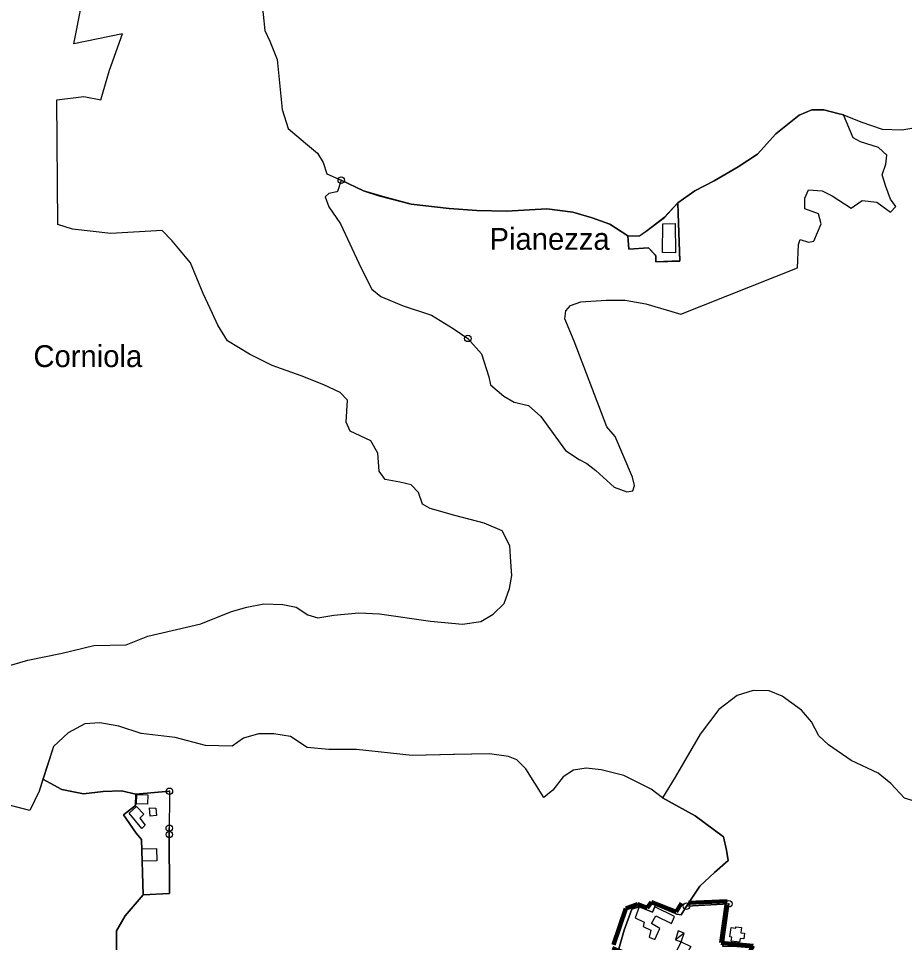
# Model space of a CAD drawing. Extents: x 645880 to 658994, y 884400 to 894744.
# Drawn here: x 655833 to 656523, y 890454 to 891174 of the extents above; entities that cross this region are included whole.
import ezdxf
from ezdxf.enums import TextEntityAlignment as Align

# ---------------------------------------------------------------- set-up
doc = ezdxf.new("R2010")
doc.units = 0
doc.header["$LTSCALE"] = 10
doc.header["$PDMODE"] = 32
doc.header["$PDSIZE"] = 5
doc.linetypes.add('MEDIUM_DASHED', pattern=[4.5, 3, -1.5])
for name, color, linetype, lineweight in [('1', 7, 'Continuous', 25), ('15', 7, 'MEDIUM_DASHED', 100), ('16', 7, 'Continuous', 25), ('18', 7, 'Continuous', 25), ('4', 7, 'Continuous', 25), ('6', 7, 'Continuous', 25)]:
    doc.layers.add(name, color=color, linetype=linetype, lineweight=lineweight)
doc.layers.add('60', color=7, linetype='Continuous')

msp = doc.modelspace()

# ---------------------------------------------------------------- linework, layer by layer
at = {"layer": '1'}
msp.add_line((656351.51, 890461.61), (656344.76, 890456.42), dxfattribs=at)
for points in [[(656316.6, 890482.09), (656310.86, 890480.17), (656304.84, 890463.75), (656300.81, 890449.21), (656323.09, 890440.57), (656323.73, 890436.19), (656329.95, 890433.47)], [(656405.68, 890449.96), (656389.24, 890451.06), (656381.68, 890451.17), (656386.34, 890484.41), (656353.4, 890482.51), (656349.21, 890475.84), (656345.83, 890476.36), (656329.38, 890483.21), (656326.8, 890477.93), (656316.6, 890482.09)]]:
    msp.add_lwpolyline(points, dxfattribs=at)
for points in [[(656316.6, 890482.09), (656313.35, 890473.44), (656320.38, 890469.97), (656319.66, 890466.8), (656325.73, 890463.8), (656324.31, 890458.49), (656328.63, 890456.66), (656332.61, 890465.13), (656326.16, 890469.05), (656329.4, 890475.07), (656341.7, 890469.11), (656344.17, 890474.39), (656328.63, 890481.92), (656326.8, 890477.93)], [(656344.76, 890456.42), (656349.18, 890454.85), (656351.51, 890461.61), (656346.96, 890463.4)], [(656350.13, 890439.21), (656343.19, 890442.63), (656349.15, 890454.85), (656356.76, 890451.16)]]:
    msp.add_lwpolyline(points, close=True, dxfattribs=at)
at = {"layer": '15'}
msp.add_lwpolyline([(656326.91, 890431.81), (656332.62, 890438.94), (656354.72, 890428.62), (656352.4, 890422.3), (656367.55, 890416.83), (656382.07, 890417.25), (656391.12, 890427.78), (656405.22, 890451.78), (656380.39, 890453.89), (656385.02, 890486.31), (656349.54, 890484.92), (656345.25, 890478.1), (656326.1, 890485.68), (656322.73, 890481.26), (656315.36, 890484.21), (656306.1, 890480.84), (656295.79, 890450.1), (656318.73, 890439.78), (656320.46, 890435.07)], close=True, dxfattribs=at)
at = {"layer": '16'}
msp.add_line((656386.34, 890484.41), (656381.68, 890451.17), dxfattribs=at)
for points in [[(656107.51, 890844.89), (656091.53, 890852.4), (656088.44, 890859.4), (656089.47, 890876.4), (656083.8, 890882.4), (656070.91, 890888.4), (656053.38, 890895.4), (656030.7, 890903.41), (656013.18, 890912.12), (655996, 890922.49), (655988.42, 890934.91), (655984.3, 890943.92), (655977.08, 890959.42), (655967.29, 890983.42), (655952.85, 891000.43), (655945.15, 891008.51), (655905.11, 891006.15), (655875.32, 891009.61), (655863.98, 891013.11), (655863.11, 891110.32), (655884.21, 891112.73), (655897.47, 891110.32), (655904.1, 891133.25), (655914.35, 891161.62), (655876.33, 891153.86), (655882.51, 891185.32)], [(656022.57, 891189.45), (656025.05, 891164.29), (656028.95, 891155.9), (656034.63, 891141.71), (656038.53, 891102.67), (656043.15, 891087.83), (656056.63, 891076.54), (656066.21, 891068.79)], [(656346.76, 891030.15), (656359.82, 891039.27), (656374.91, 891047.18), (656393.59, 891057.96), (656408.69, 891068.03), (656423.06, 891083.85), (656441.02, 891098.23), (656451.08, 891102.54), (656460.42, 891102.54), (656471.2, 891099.67), (656475.55, 891098.58), (656489.19, 891092.99), (656505.69, 891087.49), (656521.15, 891086.99), (656530.43, 891088.49), (656539.2, 891093.99), (656550.54, 891114), (656575.8, 891148.01)], [(656471.2, 891099.67), (656460.42, 891102.54), (656451.08, 891102.54), (656441.02, 891098.23), (656423.06, 891083.85), (656408.69, 891068.03), (656393.59, 891057.96), (656374.91, 891047.18), (656359.82, 891039.27), (656346.76, 891030.15), (656346.97, 891021.75), (656347.02, 891021.8), (656348.15, 890984.82), (656329.53, 890984.13), (656329.53, 890988.93), (656323.82, 890995.11), (656308.49, 890993.97), (656307.81, 891004.27)], [(656466.77, 891035.6), (656481.67, 891025.92), (656490.18, 891031.73), (656501.54, 891030.43), (656512.18, 891022.69), (656516.44, 891027.21), (656512.18, 891033.02), (656508.63, 891042.69), (656505.79, 891051.73), (656508.63, 891060.12), (656509.34, 891067.21), (656502.95, 891073.02), (656488.76, 891077.54), (656483.09, 891080.76), (656475.55, 891098.58), (656471.2, 891099.67)], [(656066.21, 891068.79), (656070.39, 891061.56), (656073.22, 891052.53), (656084.58, 891047.69)], [(656116.93, 891034.95), (656101.84, 891039.27), (656084.58, 891047.69), (656081.74, 891038.98), (656081.03, 891038.65), (656075, 891037.36), (656072.16, 891034.78), (656075, 891027.04), (656083.87, 891013.81), (656100.19, 890979.29), (656108.35, 890962.84), (656115.44, 890957.03), (656132.76, 890949.96), (656154.75, 890942.54), (656171.78, 890932.22), (656183.14, 890924.48)], [(656084.58, 891047.69), (656101.84, 891039.27), (656113.9, 891035.54), (656139.05, 891029.07)], [(656183.14, 890924.48), (656193.78, 890912.54), (656199.46, 890894.48), (656200.88, 890888.35), (656211.17, 890879.63), (656219.33, 890874.8), (656230.32, 890872.21), (656239.9, 890863.83), (656259.06, 890837.37), (656269.71, 890830.27), (656275.74, 890827.05), (656282.83, 890821.56), (656297.03, 890808.66), (656306.96, 890805.11), (656311.57, 890805.76), (656312.99, 890809.95), (656311.22, 890816.4), (656297.73, 890848.02), (656291.35, 890855.76), (656265.83, 890922.44), (656258.73, 890939.86), (656259.44, 890945.99), (656262.99, 890950.18), (656271.15, 890953.09), (656290.75, 890954.4), (656305.7, 890954.4), (656321.68, 890951.4), (656348.97, 890943.33), (656439.8, 890979.46), (656440.51, 890997.53), (656441.93, 891001.4), (656448.32, 890999.46), (656452.57, 891000.11), (656458.25, 891013.66), (656456.12, 891021.4), (656445.48, 891025.27), (656445.48, 891033.66), (656448.32, 891040.11), (656458.96, 891039.47), (656466.77, 891035.6)], [(656190.08, 891024.04), (656168.67, 891025.61), (656139.05, 891029.07), (656116.93, 891034.95)], [(656139.05, 891029.07), (656168.67, 891025.61), (656190.08, 891024.04), (656213.23, 891023.45), (656244.69, 891025.48), (656264.97, 891022.73), (656280.06, 891018.42), (656293.71, 891013.38), (656307.81, 891004.27), (656316.73, 891004.27), (656322.67, 891008.39), (656336.16, 891018.69), (656346.76, 891030.15)], [(656307.81, 891004.27), (656293.71, 891013.38), (656280.06, 891018.42), (656264.97, 891022.73), (656244.69, 891025.48), (656213.23, 891023.45), (656190.08, 891024.04)], [(655792.34, 890660.05), (655840.64, 890674.02), (655867.17, 890679.45), (655892.03, 890685.35), (655917.21, 890686.09), (655934.03, 890692.7), (655975.29, 890702.29), (655999.14, 890712.01), (656010.98, 890715.31), (656024.41, 890717.97), (656038.96, 890717.41), (656049.45, 890715.17), (656058.55, 890709.29), (656066.25, 890707.05), (656078.7, 890709.01), (656098.15, 890710.97), (656114.24, 890710.13), (656154.01, 890704.34), (656178.9, 890702.01), (656193.15, 890704.08), (656202.75, 890709.79), (656211.3, 890718.09), (656215.45, 890729.77), (656217.27, 890739.88), (656216.49, 890750.52), (656215.76, 890763.07), (656209.75, 890774.65), (656195.75, 890780.62), (656172.97, 890786.57), (656153.9, 890792.07), (656147.71, 890795.57), (656144.62, 890804.57), (656138.95, 890810.58), (656130.18, 890812.58), (656118.84, 890814.58), (656114.2, 890821.08), (656113.17, 890835.08), (656107.51, 890844.89)], [(656535.88, 890562.67), (656523.1, 890566.68), (656512.58, 890577.96), (656502.75, 890586.03), (656481.61, 890596.03), (656464.08, 890608.04), (656456.35, 890615.04), (656450.68, 890626.04), (656442.94, 890635.04), (656427.99, 890646.04), (656417.68, 890650.04), (656405.31, 890650.54), (656392.94, 890646.54), (656378.5, 890635.54), (656364.13, 890616.47), (656344.54, 890582.96), (656334.72, 890566.93)], [(656228.32, 890589.55), (656221.24, 890596.51), (656214.92, 890599.06), (656200.11, 890601.09), (656171.99, 890600.59), (656139.82, 890599.76), (656096.48, 890604.59), (656074.95, 890604.53), (656058.16, 890606.03), (656044.93, 890614.6), (656032.04, 890616.6), (656020.18, 890616.6), (656008.57, 890613.31), (655999.55, 890607.04), (655978.76, 890607.54), (655955.21, 890613.81), (655928.66, 890616.82), (655911.37, 890622.58), (655896.59, 890625.34), (655884.87, 890624.5), (655871.98, 890617.5), (655860.52, 890606.79), (655852.28, 890581.39)], [(656353.4, 890482.51), (656363.66, 890498.23), (656375.28, 890508.69), (656385.73, 890517.99), (656384.57, 890526.12), (656382.25, 890536.58), (656360.18, 890552.86), (656334.72, 890566.93), (656325.76, 890573.55), (656304.66, 890584.23), (656286.87, 890588.74), (656275.35, 890589.99), (656265.33, 890588.49), (656257.31, 890583.22), (656249.3, 890572.95), (656242.24, 890567.05), (656228.32, 890589.55)], [(655899.22, 890571.74), (655883.91, 890570.04), (655866.9, 890573.44), (655852.28, 890581.39), (655849.3, 890571.99), (655842.21, 890557.03), (655811.7, 890564.82)], [(655852.28, 890581.39), (655866.9, 890573.44), (655883.91, 890570.04), (655899.22, 890571.74), (655913.39, 890572.31), (655924.68, 890569.8), (655950.79, 890571.98), (655950.69, 890538.37)], [(655915.26, 890336.66), (655917.59, 890354.1), (655917.59, 890383.15), (655921.07, 890399.43), (655915.26, 890415.7), (655909.46, 890436.62), (655909.46, 890463.36), (655916.43, 890474.98), (655930.3, 890491.47), (655928.97, 890534.53), (655925.01, 890539.27), (655915.12, 890553.65), (655924.48, 890560.83), (655924.68, 890569.8), (655913.39, 890572.31), (655899.22, 890571.74)], [(656334.72, 890566.93), (656360.18, 890552.86), (656382.25, 890536.58), (656384.57, 890526.12), (656385.73, 890517.99), (656375.28, 890508.69), (656363.66, 890498.23), (656353.4, 890482.51), (656386.34, 890484.41)], [(655950.69, 890538.37), (655950.79, 890492.47), (655930.3, 890491.47)], [(655930.3, 890491.47), (655916.43, 890474.98), (655909.46, 890463.36), (655909.46, 890436.62), (655915.26, 890415.7), (655921.07, 890399.43), (655917.59, 890383.15), (655917.59, 890354.1), (655915.26, 890336.66), (655908.48, 890319.27)], [(656300.81, 890449.21), (656304.84, 890463.75), (656310.86, 890480.17), (656315.7, 890481.79)], [(656315.7, 890481.79), (656315.81, 890482.09), (656316.17, 890481.94)], [(656316.17, 890481.94), (656316.6, 890482.09), (656326.8, 890477.93), (656329.38, 890483.21)], [(656329.38, 890483.21), (656345.83, 890476.36), (656349.21, 890475.84), (656353.4, 890482.51)]]:
    msp.add_lwpolyline(points, dxfattribs=at)
for p in [(656084.58, 891047.69), (656183.14, 890924.48), (655950.69, 890538.37), (656386.34, 890484.41), (656353.4, 890482.51)]:
    msp.add_point(p, dxfattribs=at)
at = {"layer": '18'}
for points in [[(655863.98, 891013.11), (655863.11, 891110.32), (655884.21, 891112.73), (655897.47, 891110.32), (655904.1, 891133.25), (655914.35, 891161.62), (655876.33, 891153.86), (655882.51, 891185.32)], [(656022.57, 891189.45), (656025.05, 891164.29), (656028.95, 891155.9), (656034.63, 891141.71), (656038.53, 891102.67), (656043.15, 891087.83), (656056.63, 891076.54), (656066.21, 891068.79), (656070.39, 891061.56), (656073.22, 891052.53), (656084.58, 891047.69), (656081.74, 891038.98), (656081.03, 891038.65), (656075, 891037.36), (656072.16, 891034.78), (656075, 891027.04), (656083.87, 891013.81), (656100.19, 890979.29), (656108.35, 890962.84), (656115.44, 890957.03), (656132.76, 890949.96), (656154.75, 890942.54), (656171.78, 890932.22), (656183.14, 890924.48), (656193.78, 890912.54), (656199.46, 890894.48)], [(656490.18, 891031.73), (656501.54, 891030.43), (656512.18, 891022.69), (656516.44, 891027.21), (656512.18, 891033.02), (656508.63, 891042.69), (656505.79, 891051.73), (656508.63, 891060.12), (656509.34, 891067.21), (656502.95, 891073.02), (656488.76, 891077.54), (656483.09, 891080.76), (656475.55, 891098.58), (656489.19, 891092.99), (656505.69, 891087.49), (656521.15, 891086.99), (656530.43, 891088.49)], [(656199.46, 890894.48), (656200.88, 890888.35), (656211.17, 890879.63), (656219.33, 890874.8), (656230.32, 890872.21), (656239.9, 890863.83), (656259.06, 890837.37), (656269.71, 890830.27), (656275.74, 890827.05), (656282.83, 890821.56), (656297.03, 890808.66), (656306.96, 890805.11), (656311.57, 890805.76), (656312.99, 890809.95), (656311.22, 890816.4), (656297.73, 890848.02), (656291.35, 890855.76), (656265.83, 890922.44), (656258.73, 890939.86), (656259.44, 890945.99), (656262.99, 890950.18), (656271.15, 890953.09), (656290.75, 890954.4), (656305.7, 890954.4), (656321.68, 890951.4), (656348.97, 890943.33), (656439.8, 890979.46), (656440.51, 890997.53), (656441.93, 891001.4), (656448.32, 890999.46), (656452.57, 891000.11), (656458.25, 891013.66), (656456.12, 891021.4), (656445.48, 891025.27), (656445.48, 891033.66), (656448.32, 891040.11), (656458.96, 891039.47), (656466.77, 891035.6), (656481.67, 891025.92), (656490.18, 891031.73)], [(656107.51, 890844.89), (656091.53, 890852.4), (656088.44, 890859.4), (656089.47, 890876.4), (656083.8, 890882.4), (656070.91, 890888.4), (656053.38, 890895.4), (656030.7, 890903.41), (656013.18, 890912.12), (655996, 890922.49), (655988.42, 890934.91), (655984.3, 890943.92), (655977.08, 890959.42), (655967.29, 890983.42), (655952.85, 891000.43), (655945.15, 891008.51), (655905.11, 891006.15), (655875.32, 891009.61), (655863.98, 891013.11)], [(655792.34, 890660.05), (655840.64, 890674.02), (655867.17, 890679.45), (655892.03, 890685.35), (655917.21, 890686.09), (655934.03, 890692.7), (655975.29, 890702.29), (655999.14, 890712.01), (656010.98, 890715.31), (656024.41, 890717.97), (656038.96, 890717.41), (656049.45, 890715.17), (656058.55, 890709.29), (656066.25, 890707.05), (656078.7, 890709.01), (656098.15, 890710.97), (656114.24, 890710.13), (656154.01, 890704.34), (656178.9, 890702.01), (656193.15, 890704.08), (656202.75, 890709.79), (656211.3, 890718.09), (656215.45, 890729.77), (656217.27, 890739.88), (656216.49, 890750.52), (656215.76, 890763.07), (656209.75, 890774.65), (656195.75, 890780.62), (656172.97, 890786.57), (656153.9, 890792.07), (656147.71, 890795.57), (656144.62, 890804.57), (656138.95, 890810.58), (656130.18, 890812.58), (656118.84, 890814.58), (656114.2, 890821.08), (656113.17, 890835.08), (656107.51, 890844.89)], [(656535.88, 890562.67), (656523.1, 890566.68), (656512.58, 890577.96), (656502.75, 890586.03), (656481.61, 890596.03), (656464.08, 890608.04), (656456.35, 890615.04), (656450.68, 890626.04), (656442.94, 890635.04), (656427.99, 890646.04), (656417.68, 890650.04), (656405.31, 890650.54), (656392.94, 890646.54), (656378.5, 890635.54), (656364.13, 890616.47), (656344.54, 890582.96), (656334.72, 890566.93), (656325.76, 890573.55), (656304.66, 890584.23), (656286.87, 890588.74), (656275.35, 890589.99), (656265.33, 890588.49), (656257.31, 890583.22), (656249.3, 890572.95), (656242.24, 890567.05), (656228.32, 890589.55)], [(656228.32, 890589.55), (656221.24, 890596.51), (656214.92, 890599.06), (656200.11, 890601.09), (656172.78, 890600.59), (656139.82, 890599.76), (656096.48, 890604.59), (656074.95, 890604.53), (656058.16, 890606.03), (656044.93, 890614.6), (656032.04, 890616.6), (656020.18, 890616.6), (656008.57, 890613.31), (655999.55, 890607.04), (655978.76, 890607.54), (655955.21, 890613.81), (655928.66, 890616.82), (655911.37, 890622.58), (655896.59, 890625.34), (655884.87, 890624.5), (655871.98, 890617.5), (655860.52, 890606.79), (655855.51, 890591.25), (655849.3, 890571.99), (655842.21, 890557.03), (655811.7, 890564.82)]]:
    msp.add_lwpolyline(points, dxfattribs=at)
at = {"layer": '4'}
for points in [[(656346.91, 891021.65), (656346.7, 891030.05), (656336.1, 891018.59), (656322.61, 891008.29), (656316.67, 891004.17), (656307.75, 891004.17), (656308.43, 890993.87), (656323.76, 890995.01), (656329.47, 890988.83), (656329.47, 890984.03)], [(656329.47, 890984.03), (656348.09, 890984.72), (656346.96, 891021.7)], [(655950.79, 890571.98), (655924.68, 890569.8), (655924.48, 890560.83), (655915.12, 890553.65), (655925.01, 890539.27), (655928.97, 890534.53)], [(655928.97, 890534.53), (655930.3, 890491.47), (655950.79, 890492.47), (655950.69, 890538.37), (655950.68, 890543.22)]]:
    msp.add_lwpolyline(points, dxfattribs=at)
for points in [[(656335.02, 891013.64), (656344.44, 891013.88), (656344.92, 890991.18), (656334.78, 890991.42)], [(655925.36, 890569.4), (655933.85, 890569.2), (655933.65, 890562.03), (655925.28, 890562.23)], [(655925.28, 890560.03), (655930.86, 890554.25), (655927.67, 890551.06), (655931.8, 890545.64), (655929.2, 890543.03), (655919.5, 890555.05)], [(655935.32, 890558.97), (655940.23, 890558.84), (655940.69, 890553), (655935.78, 890552.69)], [(655929.47, 890527.13), (655940.82, 890527.33), (655941.02, 890517.76), (655929.67, 890517.56)]]:
    msp.add_lwpolyline(points, close=True, dxfattribs=at)
for p in [(655950.79, 890571.98), (655950.68, 890543.22)]:
    msp.add_point(p, dxfattribs=at)
at = {"layer": '6'}
msp.add_lwpolyline([(656387.15, 890458.59), (656388.22, 890466.01), (656391.68, 890465.51), (656391.83, 890466.5), (656396.28, 890465.86), (656395.71, 890461.9), (656398.68, 890461.48), (656398.04, 890457.02), (656395.07, 890457.45), (656394.65, 890454.48), (656388.21, 890455.4), (656388.64, 890458.37)], close=True, dxfattribs=at)

# ---------------------------------------------------------------- texts
at = {"layer": '60'}
for s, p in [('Pianezza', (656246.81, 890993.47)), ('Corniola', (655887.24, 890902.2))]:
    msp.add_text(s, height=17, dxfattribs=at).set_placement(p, align=Align.CENTER)

doc.saveas('drawing.dxf')
